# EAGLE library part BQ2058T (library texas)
CHARGE MANAGEMENT IC
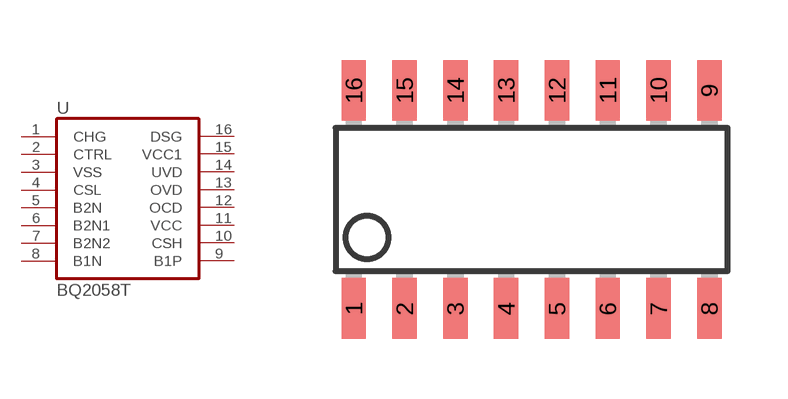
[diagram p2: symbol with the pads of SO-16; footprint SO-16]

Designator prefix U

## BQ2058T (OC_FARNELL: unknown; OC_NEWARK: unknown)  [SO-16]
1  CHG  hiz
2  CTRL  in
3  VSS  pwr
4  CSL  in
5  B2N  in
6  B2N1  in
7  B2N2  in
8  B1N  in
9  B1P  in
10  CSH  in
11  VCC  pwr
12  OCD  in
13  OVD  in
14  UVD  in
15  VCC1  pwr
16  DSG  out

## Footprint SO-16 (pad centres in mm)
Small Outline Integrated Circuit
smd 0.61 x 1.524: 1 -4.445,-2.794; 2 -3.175,-2.794; 3 -1.905,-2.794; 4 -0.635,-2.794; 5 0.635,-2.794; 6 1.905,-2.794; 7 3.175,-2.794; 8 4.445,-2.794; 9 4.445,2.667; 10 3.175,2.667; 11 1.905,2.667; 12 0.635,2.667; 13 -0.635,2.667; 14 -1.905,2.667; 15 -3.175,2.667; 16 -4.445,2.667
